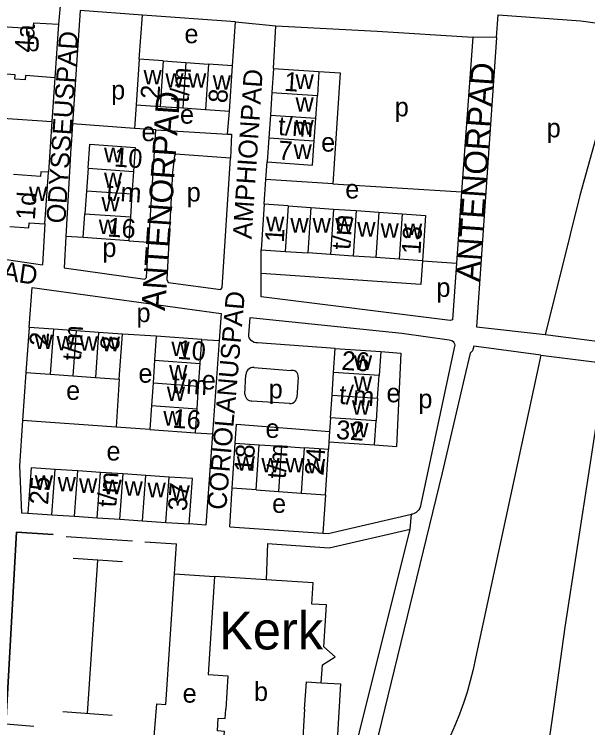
# Model space of a CAD drawing. Extents: x 161773 to 163836, y 384796 to 386521.
# Drawn here: x 162125.5 to 162246.8, y 385996.1 to 386146.9 of the extents above; entities that cross this region are included whole.
import ezdxf

# ---------------------------------------------------------------- set-up
doc = ezdxf.new("R2010")
doc.units = 0
for name, color, linetype in [('BLT_Basislijn', 7, 'Continuous'), ('BLT_Bebouwing', 7, 'Continuous'), ('BLT_Bebouwing_beschrifting', 7, 'Continuous'), ('BLT_Centroide', 7, 'Continuous'), ('BLT_Huisnummer', 7, 'Continuous'), ('BLT_Huisnummer_reeks', 7, 'Continuous'), ('BLT_Onderverdeling_panden', 7, 'Continuous'), ('BLT_Straatnaam', 7, 'Continuous'), ('BLT_Straatnaam_verkleind', 7, 'Continuous'), ('BLT_Vlakafsluiter', 7, 'Continuous')]:
    doc.layers.add(name, color=color, linetype=linetype)

msp = doc.modelspace()

# ---------------------------------------------------------------- linework, layer by layer
at = {"layer": 'BLT_Basislijn'}
for p, q in [((162135.28, 386149.51), (162134.84, 386144.81)), ((162151.93, 386137.41), (162152.6, 386146.77)), ((162171.66, 386136.04), (162172.29, 386145.37)), ((162172.29, 386145.37), (162180.81, 386144.5)), ((162227.46, 386142.02), (162222.45, 386142.11)), ((162189.94, 386134.81), (162194.45, 386134.54)), ((162194.45, 386134.54), (162192.89, 386111.05)), ((162134.08, 386133.53), (162133.44, 386124.28)), ((162151.25, 386127.81), (162150.89, 386122.81)), ((162123.07, 386124.99), (162133.44, 386124.28)), ((162170.58, 386121.59), (162170.99, 386126.45)), ((162133.44, 386124.28), (162132.7, 386113.53)), ((162150.89, 386122.81), (162137.81, 386123.74)), ((162155.45, 386122.49), (162150.89, 386122.81)), ((162178.73, 386112.03), (162178.99, 386115.71)), ((162178.36, 386106.76), (162178.73, 386112.03)), ((162192.89, 386111.05), (162178.73, 386112.03)), ((162192.89, 386111.05), (162220.11, 386109.41)), ((162131.95, 386102.6), (162131.45, 386093.97)), ((162140.09, 386099.71), (162136.42, 386099.97)), ((162100.82, 386098.4), (162131.45, 386093.97)), ((162149.7, 386099.06), (162153.94, 386098.76)), ((162177.72, 386092.13), (162177.7, 386097.14)), ((162211.82, 386094.79), (162219.02, 386094.29)), ((162177.74, 386087.18), (162177.72, 386092.13)), ((162128.64, 386080.7), (162129.24, 386089.18)), ((162155.53, 386078.84), (162148.41, 386079.31)), ((162207.43, 386079.48), (162217.48, 386078.08)), ((162237.78, 386079.23), (162251.43, 386077.47)), ((162165.17, 386078.16), (162168.82, 386077.92)), ((162193.39, 386076.26), (162176.96, 386077.49)), ((162202.99, 386075.6), (162207.23, 386075.26)), ((162207.23, 386075.26), (162206.31, 386055.51)), ((162218.52, 386076.37), (162211.5, 386043.32)), ((162236.88, 386074.82), (162223.05, 386010.76)), ((162236.88, 386074.82), (162250.57, 386073.14)), ((162176.2, 386072.25), (162184.02, 386071.61)), ((162174.27, 386066.63), (162174.47, 386070.71)), ((162147.71, 386069.77), (162147.04, 386059.63)), ((162185.52, 386070.22), (162185.22, 386065.93)), ((162249.79, 386068.11), (162241.92, 386017.31)), ((162183.73, 386064.64), (162175.76, 386065.14)), ((162147.04, 386059.63), (162127.26, 386061.02)), ((162154.17, 386059.13), (162147.04, 386059.63)), ((162163.81, 386058.45), (162167.39, 386058.2)), ((162192.02, 386056.54), (162191.95, 386054.91)), ((162201.66, 386055.89), (162206.31, 386055.51)), ((162191.29, 386045.33), (162190.73, 386037.23)), ((162136.49, 386036.53), (162150.53, 386035.62)), ((162159.35, 386028.61), (162159.77, 386034.92)), ((162140.99, 385999.1), (162143.15, 386031.5)), ((162154.55, 385987.69), (162155.61, 386001.09))]:
    msp.add_line(p, q, dxfattribs=at)
for points in [[(162139.45, 386147.7), (162137.81, 386123.74)], [(162152.6, 386146.77), (162139.45, 386147.7)], [(162172.29, 386145.37), (162152.6, 386146.77)], [(162227.46, 386142.02), (162227.85, 386146.84), (162245.3, 386145.55)], [(162245.3, 386145.55), (162304.99, 386137.39)], [(162180.35, 386135.47), (162180.81, 386144.5)], [(162180.81, 386144.5), (162202.25, 386143.38), (162222.45, 386142.11)], [(162222.45, 386142.11), (162220.11, 386109.41)], [(162227.46, 386142.02), (162223.27, 386080.86), (162237.78, 386079.23)], [(162254.86, 386140.04), (162248.46, 386120.76), (162246.78, 386114.69), (162245.11, 386108.63)], [(162137.81, 386123.74), (162137.51, 386119.24), (162137.47, 386118.69)], [(162153.94, 386098.76), (162155.45, 386122.49)], [(162155.45, 386122.49), (162170.58, 386121.59)], [(162170.58, 386121.59), (162171.44, 386121.55), (162171.21, 386116.52)], [(162137.47, 386118.69), (162136.42, 386099.97)], [(162171.21, 386116.52), (162159.56, 386117.32), (162159.4, 386117.08), (162158.93, 386113.48), (162157.77, 386090.83), (162158.05, 386090.25), (162169.15, 386088.75)], [(162169.15, 386088.75), (162169.47, 386089.13), (162171.21, 386116.52)], [(162220.11, 386109.41), (162219.02, 386094.29)], [(162245.11, 386108.63), (162240.99, 386092.1), (162237.78, 386079.23)], [(162136.42, 386099.97), (162136.05, 386093.29), (162153.11, 386090.95), (162153.43, 386091.27), (162153.63, 386093.91), (162153.94, 386098.76)], [(162211.82, 386094.79), (162211.48, 386089.8), (162177.72, 386092.13)], [(162219.02, 386094.29), (162218.17, 386082.34), (162217.69, 386082.15), (162177.74, 386087.18)], [(162129.24, 386089.18), (162169.24, 386083.69)], [(162169.24, 386083.69), (162168.82, 386077.92)], [(162175.07, 386079.18), (162175.35, 386082.85)], [(162175.35, 386082.85), (162207.43, 386079.48)], [(162176.96, 386077.49), (162176.59, 386077.49), (162176.23, 386077.56), (162175.89, 386077.72), (162175.6, 386077.94), (162175.36, 386078.22), (162175.19, 386078.55), (162175.09, 386078.9), (162175.07, 386079.18)], [(162222.66, 386076.72), (162222.42, 386075.78), (162221.94, 386075.27), (162220.69, 386070.17), (162216.01, 386049.98), (162197.07, 385972.43), (162167.75, 385940.71), (162164.04, 385930.05), (162159.87, 385872.82), (162161.24, 385746.35)], [(162168.82, 386077.92), (162167.39, 386058.2)], [(162217.48, 386078.08), (162217.78, 386078.05), (162218.06, 386077.95), (162218.31, 386077.77), (162218.49, 386077.53), (162218.62, 386077.25), (162218.66, 386076.95), (162218.63, 386076.65), (162218.52, 386076.37)], [(162236.88, 386074.82), (162222.66, 386076.72)], [(162176.2, 386072.25), (162175.84, 386072.24), (162175.49, 386072.14), (162175.18, 386071.98), (162174.9, 386071.74), (162174.69, 386071.46), (162174.54, 386071.13), (162174.47, 386070.71)], [(162127.97, 386071.16), (162127.26, 386061.02)], [(162185.52, 386070.22), (162185.52, 386070.53), (162185.45, 386070.84), (162185.3, 386071.11), (162185.08, 386071.35), (162184.82, 386071.52), (162184.52, 386071.61), (162184.2, 386071.63), (162184.02, 386071.61)], [(162174.27, 386066.63), (162174.32, 386066.28), (162174.44, 386065.96), (162174.64, 386065.67), (162174.89, 386065.43), (162175.2, 386065.26), (162175.53, 386065.16), (162175.76, 386065.14)], [(162183.73, 386064.64), (162184.05, 386064.64), (162184.37, 386064.73), (162184.66, 386064.89), (162184.9, 386065.11), (162185.08, 386065.39), (162185.19, 386065.7), (162185.22, 386065.93)], [(162127.26, 386061.02), (162126.59, 386051.48)], [(162172.19, 386056.27), (162172.46, 386060.28)], [(162172.46, 386060.28), (162192.17, 386058.71)], [(162167.39, 386058.2), (162165.98, 386038.9), (162162.5, 386039.16)], [(162126.59, 386051.48), (162127.02, 386041.54), (162128.39, 386041.45)], [(162171.06, 386038.58), (162171.55, 386046.69)], [(162211.5, 386043.32), (162211.44, 386042.91), (162211.3, 386042.51), (162211.08, 386042.14), (162210.8, 386041.83), (162210.47, 386041.57), (162210.09, 386041.37), (162209.69, 386041.26), (162209.51, 386041.23)], [(162190.73, 386037.23), (162191.86, 386037.15), (162209.51, 386041.23)], [(162151.41, 385938.24), (162161.22, 385934.09), (162161.96, 385934.17), (162164.25, 385942.46), (162193.53, 385975.09), (162209.23, 386038.09)], [(162171.06, 386038.58), (162190.73, 386037.23)], [(162179.06, 386035.02), (162192.1, 386034.13), (162209.23, 386038.09)], [(162123.73, 385996.9), (162125.94, 386037.42), (162133.7, 386036.9), (162125.94, 386037.42), (162123.73, 385996.9), (162129.65, 385996.43)], [(162153.1, 386035.41), (162153.1, 386035.41), (162159.77, 386034.92)], [(162179.06, 386035.02), (162178.75, 386027.36)], [(162148.39, 386031.12), (162137.92, 386031.88)], [(162155.61, 386001.09), (162157.55, 386000.96), (162159.35, 386028.61)], [(162159.35, 386028.61), (162167.81, 386028.06)], [(162241.92, 386017.31), (162239.68, 386001.07), (162237.2, 385983.86), (162232.1, 385954.86), (162226.57, 385926.28)], [(162223.05, 386010.76), (162222.53, 386008.35), (162221.93, 386005.96), (162221.25, 386003.6), (162220.49, 386001.25), (162219.67, 385998.93), (162218.76, 385996.65), (162217.78, 385994.39), (162216.73, 385992.16), (162215.61, 385989.97), (162214.41, 385987.82), (162213.15, 385985.7), (162211.82, 385983.63), (162210.42, 385981.6), (162208.96, 385979.62), (162207.43, 385977.69), (162206.75, 385976.87)], [(162190.42, 386005.59), (162194.48, 386005.35), (162193.21, 385983.74), (162188.76, 385975.15), (162181.57, 385975.58)], [(162135.78, 385999.48), (162146.21, 385998.72)]]:
    msp.add_lwpolyline(points, dxfattribs=at)
at = {"layer": 'BLT_Bebouwing'}
for p, q in [((162134.84, 386144.81), (162134.08, 386133.53)), ((162157, 386137.06), (162161.79, 386136.73)), ((162161.79, 386136.73), (162166.58, 386136.39)), ((162171.66, 386136.04), (162166.58, 386136.39)), ((162180.35, 386135.47), (162180, 386130.4)), ((162180.35, 386135.47), (162189.94, 386134.81)), ((162180, 386130.4), (162179.67, 386125.61)), ((162189.26, 386124.95), (162189.59, 386129.74)), ((162156.33, 386127.46), (162161.12, 386127.13)), ((162161.12, 386127.13), (162165.91, 386126.8)), ((162179.67, 386125.61), (162179.34, 386120.81)), ((162188.93, 386120.15), (162189.26, 386124.95)), ((162179.34, 386120.81), (162178.99, 386115.71)), ((162141.11, 386114.37), (162140.77, 386109.56)), ((162150.69, 386113.71), (162150.36, 386108.9)), ((162140.77, 386109.56), (162140.44, 386104.76)), ((162150.36, 386108.9), (162150.04, 386104.1)), ((162178.36, 386106.76), (162177.7, 386097.14)), ((162183.43, 386106.41), (162178.36, 386106.76)), ((162183.43, 386106.41), (162188.23, 386106.08)), ((162188.23, 386106.08), (162193.03, 386105.74)), ((162193.03, 386105.74), (162197.82, 386105.41)), ((162197.82, 386105.41), (162202.59, 386105.09)), ((162202.59, 386105.09), (162207.53, 386104.75)), ((162177.7, 386097.14), (162182.77, 386096.79)), ((162182.77, 386096.79), (162187.57, 386096.46)), ((162192.38, 386096.13), (162187.57, 386096.46)), ((162197.16, 386095.8), (162192.38, 386096.13)), ((162201.93, 386095.47), (162197.16, 386095.8)), ((162206.88, 386095.13), (162201.93, 386095.47)), ((162138.55, 386080.01), (162133.76, 386080.35)), ((162143.34, 386079.67), (162138.55, 386080.01)), ((162155.18, 386073.76), (162154.85, 386068.99)), ((162164.49, 386068.31), (162164.82, 386073.09)), ((162133.06, 386070.8), (162137.85, 386070.47)), ((162192.7, 386066.39), (162193.04, 386071.18)), ((162137.85, 386070.47), (162142.64, 386070.13)), ((162202.32, 386065.73), (162202.65, 386070.52)), ((162154.85, 386068.99), (162154.52, 386064.21)), ((162164.16, 386063.53), (162164.49, 386068.31)), ((162192.37, 386061.6), (162192.7, 386066.39)), ((162202.32, 386065.73), (162202, 386060.94)), ((162177.26, 386055.92), (162182.04, 386055.59)), ((162182.04, 386055.59), (162186.85, 386055.26)), ((162129.04, 386051.03), (162128.39, 386041.45)), ((162134.12, 386050.69), (162129.04, 386051.03)), ((162138.92, 386050.37), (162134.12, 386050.69)), ((162143.71, 386050.05), (162138.92, 386050.37)), ((162148.51, 386049.73), (162143.71, 386050.05)), ((162153.31, 386049.41), (162148.51, 386049.73)), ((162158.24, 386049.08), (162153.31, 386049.41)), ((162163.17, 386048.74), (162158.24, 386049.08)), ((162176.62, 386046.34), (162171.55, 386046.69)), ((162176.62, 386046.34), (162181.4, 386046.01)), ((162181.4, 386046.01), (162186.21, 386045.68)), ((162128.39, 386041.45), (162133.45, 386041.11)), ((162133.45, 386041.11), (162138.25, 386040.78)), ((162138.25, 386040.78), (162143.04, 386040.46)), ((162143.04, 386040.46), (162147.84, 386040.14)), ((162147.84, 386040.14), (162152.64, 386039.82)), ((162152.64, 386039.82), (162157.57, 386039.49))]:
    msp.add_line(p, q, dxfattribs=at)
for points in [[(162121.79, 386144.44), (162129.51, 386143.92), (162129.6, 386145.16), (162134.84, 386144.81)], [(162134.08, 386133.53), (162127.88, 386134.01), (162127.81, 386133.08), (162125.58, 386133.23), (162125.65, 386134.16), (162121.11, 386134.47), (162121.79, 386144.44)], [(162151.93, 386137.41), (162151.25, 386127.81)], [(162157, 386137.06), (162151.93, 386137.41)], [(162170.99, 386126.45), (162171.66, 386136.04)], [(162189.94, 386134.81), (162189.59, 386129.74), (162189.59, 386129.74)], [(162151.25, 386127.81), (162156.33, 386127.46)], [(162165.91, 386126.8), (162170.99, 386126.45)], [(162141.11, 386114.37), (162141.46, 386119.44), (162151.03, 386118.78), (162150.69, 386113.71)], [(162178.99, 386115.71), (162188.58, 386115.05), (162188.93, 386120.15)], [(162132.7, 386113.53), (162131.14, 386113.64), (162131.07, 386112.63), (162125.34, 386113.03)], [(162131.95, 386102.6), (162132.7, 386113.53)], [(162140.09, 386099.71), (162140.44, 386104.76)], [(162150.04, 386104.1), (162149.7, 386099.06)], [(162207.53, 386104.75), (162212.48, 386104.41), (162211.82, 386094.79)], [(162124.53, 386102.09), (162128.6, 386101.8), (162128.67, 386102.81), (162131.95, 386102.6)], [(162149.7, 386099.06), (162140.09, 386099.71)], [(162211.82, 386094.79), (162206.88, 386095.13)], [(162128.64, 386080.7), (162127.97, 386071.16)], [(162133.76, 386080.35), (162128.64, 386080.7)], [(162148.41, 386079.31), (162143.34, 386079.67)], [(162147.71, 386069.77), (162148.41, 386079.31)], [(162155.53, 386078.84), (162155.18, 386073.76)], [(162165.17, 386078.16), (162155.53, 386078.84)], [(162164.82, 386073.09), (162165.17, 386078.16)], [(162193.04, 386071.18), (162193.39, 386076.26)], [(162193.39, 386076.26), (162202.99, 386075.6)], [(162202.99, 386075.6), (162202.65, 386070.52)], [(162127.97, 386071.16), (162133.06, 386070.8)], [(162142.64, 386070.13), (162147.71, 386069.77)], [(162154.52, 386064.21), (162154.17, 386059.13)], [(162163.81, 386058.45), (162164.16, 386063.53)], [(162192.37, 386061.6), (162192.17, 386058.71)], [(162201.66, 386055.89), (162202, 386060.94)], [(162154.17, 386059.13), (162163.81, 386058.45)], [(162192.17, 386058.71), (162192.02, 386056.54)], [(162171.55, 386046.69), (162172.19, 386056.27)], [(162172.19, 386056.27), (162177.26, 386055.92)], [(162192.02, 386056.54), (162201.66, 386055.89)], [(162191.95, 386054.91), (162186.85, 386055.26)], [(162191.29, 386045.33), (162191.95, 386054.91)], [(162162.5, 386039.16), (162163.17, 386048.74)], [(162186.21, 386045.68), (162191.29, 386045.33)], [(162157.57, 386039.49), (162160.06, 386039.32)], [(162160.06, 386039.32), (162162.5, 386039.16)], [(162167.81, 386028.06), (162166.49, 386007.3), (162170.67, 386007.04), (162170.22, 386000)], [(162178.75, 386027.36), (162167.81, 386028.06)], [(162190.42, 386005.59), (162190.66, 386009.34), (162193.39, 386011.08), (162190.97, 386013.19), (162191.52, 386022.02), (162188.45, 386022.22), (162188.74, 386026.73), (162178.75, 386027.36)], [(162186.91, 386000), (162187.27, 386005.79), (162190.42, 386005.59)], [(162169.43, 385992.59), (162169.49, 385993.64), (162169.83, 385993.61), (162169.93, 385995.3), (162168.44, 385995.4), (162168.61, 385998.09), (162170.1, 385997.99), (162170.22, 386000)], [(162186.91, 386000), (162186.37, 385991.51), (162184.08, 385991.66)]]:
    msp.add_lwpolyline(points, dxfattribs=at)
at = {"layer": 'BLT_Onderverdeling_panden'}
for p, q in [((162157, 386137.06), (162156.33, 386127.46)), ((162161.79, 386136.73), (162161.12, 386127.13)), ((162166.58, 386136.39), (162165.91, 386126.8)), ((162180, 386130.4), (162189.59, 386129.74)), ((162179.67, 386125.61), (162189.26, 386124.95)), ((162179.34, 386120.81), (162188.93, 386120.15)), ((162141.11, 386114.37), (162150.69, 386113.71)), ((162150.36, 386108.9), (162140.77, 386109.56)), ((162183.43, 386106.41), (162182.77, 386096.79)), ((162188.23, 386106.08), (162187.57, 386096.46)), ((162193.03, 386105.74), (162192.38, 386096.13)), ((162197.82, 386105.41), (162197.16, 386095.8)), ((162140.44, 386104.76), (162150.04, 386104.1)), ((162202.59, 386105.09), (162201.93, 386095.47)), ((162207.53, 386104.75), (162206.88, 386095.13)), ((162133.76, 386080.35), (162133.06, 386070.8)), ((162138.55, 386080.01), (162137.85, 386070.47)), ((162143.34, 386079.67), (162142.64, 386070.13)), ((162155.18, 386073.76), (162164.82, 386073.09)), ((162202.65, 386070.52), (162193.04, 386071.18)), ((162154.85, 386068.99), (162164.49, 386068.31)), ((162192.7, 386066.39), (162202.32, 386065.73)), ((162154.52, 386064.21), (162164.16, 386063.53)), ((162202, 386060.94), (162192.37, 386061.6)), ((162176.62, 386046.34), (162177.26, 386055.92)), ((162182.04, 386055.59), (162181.4, 386046.01)), ((162186.21, 386045.68), (162186.85, 386055.26)), ((162133.45, 386041.11), (162134.12, 386050.69)), ((162138.25, 386040.78), (162138.92, 386050.37)), ((162143.04, 386040.46), (162143.71, 386050.05)), ((162147.84, 386040.14), (162148.51, 386049.73)), ((162152.64, 386039.82), (162153.31, 386049.41)), ((162157.57, 386039.49), (162158.24, 386049.08))]:
    msp.add_line(p, q, dxfattribs=at)
at = {"layer": 'BLT_Vlakafsluiter'}
msp.add_line((162209.23, 386038.09), (162209.51, 386041.23), dxfattribs=at)

# ---------------------------------------------------------------- texts
at = {"layer": 'BLT_Bebouwing_beschrifting'}
msp.add_text('Kerk', height=8, dxfattribs=at).set_placement((162168.81, 386012.62))
at = {"layer": 'BLT_Centroide'}
for s, p in [('b', (162127.94, 386139.12)), ('e', (162161.48, 386140.81)), ('w', (162152.83, 386132.1)), ('w', (162157.45, 386131.41)), ('w', (162162.25, 386131.41)), ('w', (162167.46, 386130.97)), ('w', (162184.97, 386131.14)), ('p', (162145.98, 386128.93)), ('w', (162184.97, 386126.33)), ('p', (162205.97, 386125.35)), ('e', (162160.54, 386123.8)), ('w', (162184.97, 386121.51)), ('p', (162238.1, 386120.91)), ('e', (162152.39, 386120.1)), ('e', (162190.4, 386117.89)), ('w', (162184.56, 386116.36)), ('w', (162144.47, 386115.65)), ('w', (162144.47, 386110.37)), ('w', (162128.61, 386107.42)), ('p', (162161.96, 386107.33)), ('e', (162195.5, 386107.99)), ('w', (162143.93, 386105.24)), ('w', (162178.74, 386101.06)), ('w', (162143.35, 386100.46)), ('w', (162183.89, 386100.76)), ('w', (162188.59, 386100.76)), ('w', (162193.38, 386100.76)), ('w', (162198.04, 386099.93)), ('w', (162202.97, 386099.69)), ('w', (162207.91, 386099.62)), ('p', (162144.13, 386095.61)), ('p', (162214.78, 386087.18)), ('p', (162151.35, 386081.84)), ('w', (162129.8, 386076.14)), ('w', (162134.43, 386075.86)), ('w', (162139.32, 386075.78)), ('w', (162143.98, 386075.69)), ('w', (162158.72, 386074.64)), ('w', (162197.31, 386071.72)), ('w', (162158.24, 386069.69)), ('e', (162151.75, 386069.03)), ('e', (162165.16, 386067.59)), ('w', (162197.3, 386067.29)), ('e', (162136.46, 386065.4)), ('w', (162157.75, 386065.14)), ('p', (162179.3, 386065.72)), ('e', (162204.21, 386064.88)), ('p', (162210.96, 386063.63)), ('w', (162196.9, 386062.26)), ('w', (162157.02, 386059.97)), ('e', (162178.63, 386057.36)), ('w', (162196.55, 386057.44)), ('e', (162144.99, 386052.58)), ('w', (162172.54, 386050.42)), ('w', (162177.75, 386050.05)), ('w', (162182.84, 386050.05)), ('w', (162187.41, 386049.83)), ('w', (162129.82, 386046.34)), ('w', (162134.67, 386046.03)), ('w', (162139.19, 386045.72)), ('w', (162144.34, 386045.42)), ('w', (162148.82, 386045.12)), ('w', (162153.68, 386044.81)), ('w', (162158.75, 386044.22)), ('e', (162180.02, 386041.5)), ('b', (162176.19, 386001.73)), ('e', (162161.1, 386001.37))]:
    msp.add_text(s, height=4, dxfattribs=at).set_placement(p)
at = {"layer": 'BLT_Huisnummer'}
for s, rotation, p in [('4a', 86.3179, (162129.52, 386138.76)), ('1d', 86.3148, (162129.84, 386103.35))]:
    msp.add_text(s, height=4, rotation=rotation, dxfattribs=at).set_placement(p)
at = {"layer": 'BLT_Huisnummer_reeks'}
for s, rotation, p in [('t/m', 86.1691, (162162.37, 386128.16)), ('1', 356.2751, (162182.5, 386130.76)), ('2', 86.1656, (162156.16, 386128.89)), ('8', 86.1691, (162170.52, 386128.07)), ('t/m', 356.2751, (162181.21, 386121.41)), ('7', 356.2751, (162181.21, 386116.23)), ('10', 356.1459, (162146.53, 386114.75)), ('t/m', 356.1468, (162144.87, 386107.61)), ('16', 356.1468, (162145.11, 386099.96)), ('t/m', 86.344, (162196.55, 386097.06)), ('1', 86.2958, (162182.48, 386098.6)), ('13', 86.3465, (162211.39, 386096.1)), ('t/m', 86.1368, (162139.57, 386073.61)), ('2', 86.1404, (162132.65, 386076.66)), ('8', 86.1368, (162147.62, 386075.8)), ('10', 356.1404, (162159.93, 386074.07)), ('26', 356.1368, (162194.61, 386071.77)), ('t/m', 356.1368, (162158.79, 386066.91)), ('t/m', 356.1368, (162194.09, 386064.58)), ('16', 356.1368, (162158.88, 386059.52)), ('32', 356.1404, (162193.46, 386057.14)), ('18', 86.1423, (162176.02, 386049.97)), ('t/m', 86.1366, (162182.89, 386048.61)), ('24', 86.1366, (162190.9, 386049.28)), ('t/m', 86.1368, (162147.04, 386042.61)), ('25', 86.1368, (162132.63, 386043.13)), ('37', 86.1368, (162161.98, 386041.8))]:
    msp.add_text(s, height=4, rotation=rotation, dxfattribs=at).set_placement(p)
at = {"layer": 'BLT_Straatnaam'}
for p in [(162223.91, 386090.25), (162157.36, 386084.16)]:
    msp.add_text('ANTENORPAD', height=5, rotation=86.0017, dxfattribs=at).set_placement(p)
at = {"layer": 'BLT_Straatnaam_verkleind'}
for s, rotation, p in [('ODYSSEUSPAD', 86.0988, (162136.26, 386102.61)), ('AMPHIONPAD', 86.1686, (162175.67, 386099.33)), ('CORIOLANUSPAD', 351.9429, (162084.21, 386096.21)), ('CORIOLANUSPAD', 85.0355, (162170.29, 386042.02))]:
    msp.add_text(s, height=4, rotation=rotation, dxfattribs=at).set_placement(p)

doc.saveas('drawing.dxf')
